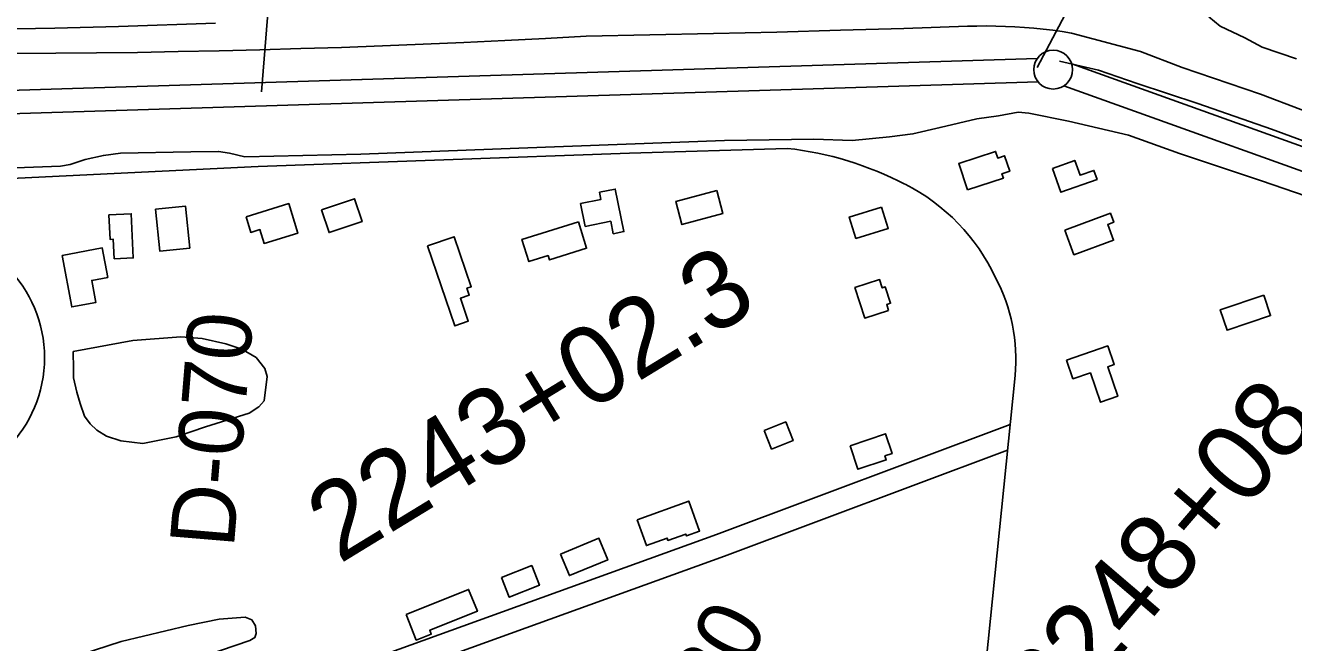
# Model space of a CAD drawing. Extents: x 3540316 to 3578335, y 553172 to 578787.
# Drawn here: x 3546126 to 3547761, y 563019 to 563815 of the extents above; entities that cross this region are included whole.
import ezdxf

# ---------------------------------------------------------------- set-up
doc = ezdxf.new("R2010")
doc.units = 0
for name, color, linetype in [('V-BLDG-OTLN', 7, 'Continuous'), ('V-FLOD-BASE', 7, 'Continuous'), ('V-LEVE-TOET', 7, 'Continuous'), ('V-RIVR-RANG', 7, 'Continuous'), ('V-RIVR-RANG-IDEN', 7, 'Continuous'), ('V-ROAD-CNTR', 7, 'Continuous'), ('V-ROAD-IDEN', 7, 'Continuous'), ('V-SITE-VEGE', 7, 'Continuous'), ('V-SURV-IDEN', 7, 'Continuous'), ('V-SURV-LINE', 7, 'Continuous'), ('V-WETL-SWMP', 7, 'Continuous')]:
    doc.layers.add(name, color=color, linetype=linetype)

msp = doc.modelspace()

# ---------------------------------------------------------------- linework, layer by layer
at = {"layer": 'V-BLDG-OTLN'}
for points in [[(3547340.8, 563603), (3547329.6, 563637.2), (3547377, 563652.8), (3547379.8, 563644.2), (3547388.7, 563647.1), (3547395.3, 563627.2), (3547385.3, 563623.9), (3547387.1, 563618.3)], [(3547450.3, 563630.9), (3547479.2, 563641.1), (3547486, 563622), (3547503.8, 563628.3), (3547507.9, 563616.7), (3547461.1, 563600.2)], [(3546847.9, 563556), (3546841.9, 563585.5), (3546868.1, 563590.9), (3546866.2, 563600), (3546886.5, 563604.1), (3546897.7, 563549.3), (3546884, 563546.5), (3546880.7, 563562.7)], [(3546507.7, 563577.6), (3546550.2, 563591.7), (3546560, 563562.3), (3546517.5, 563548.1)], [(3547017.4, 563602.4), (3547025.3, 563572.5), (3546972.4, 563558.4), (3546964.5, 563588.2)], [(3546233.5, 563571), (3546262.2, 563572.3), (3546264.8, 563515.4), (3546240.3, 563514.3), (3546239.1, 563539.5), (3546235, 563539.3)], [(3546293.6, 563578.3), (3546332.1, 563582.3), (3546337.7, 563528), (3546299.2, 563524)], [(3546410.4, 563568.6), (3546465.4, 563585.4), (3546477, 563547.3), (3546433.6, 563534.1), (3546428.2, 563552), (3546416.5, 563548.4)], [(3547230.1, 563580.8), (3547238.5, 563553.3), (3547196.8, 563540.6), (3547188.4, 563568.1)], [(3547466.3, 563551.3), (3547525.2, 563573.1), (3547529.5, 563561.5), (3547521.8, 563558.6), (3547529.3, 563538.3), (3547478.1, 563519.4)], [(3546839, 563562), (3546849.6, 563527.8), (3546801.5, 563512.8), (3546799.8, 563518.4), (3546775.1, 563510.7), (3546766.2, 563539.3)], [(3546644.2, 563530.8), (3546678.8, 563542.7), (3546700.8, 563478.3), (3546695.2, 563476.3), (3546698.2, 563467.4), (3546686.8, 563463.5), (3546697, 563433.7), (3546679.5, 563427.7)], [(3546173, 563518.6), (3546224.9, 563528.4), (3546232, 563490.3), (3546211.4, 563486.5), (3546216.7, 563458.1), (3546185.5, 563452.3)], [(3547239.1, 563447.8), (3547208.4, 563437.9), (3547195.7, 563477.2), (3547227.5, 563487.4), (3547230.9, 563476.8), (3547234.8, 563478.1), (3547241.6, 563456.9), (3547236.7, 563455.3)], [(3547722.9, 563467.5), (3547731.8, 563441), (3547675.7, 563422.1), (3547666.8, 563448.6)], [(3547468.5, 563383.6), (3547521.8, 563402), (3547530.1, 563377.9), (3547521.6, 563374.9), (3547534.7, 563337), (3547512.3, 563329.3), (3547499.3, 563367.2), (3547476.8, 563359.5)], [(3547078.5, 563292.8), (3547106.3, 563303.9), (3547115.9, 563279.9), (3547088.1, 563268.8)], [(3547189.3, 563273.3), (3547234.9, 563288.6), (3547243.5, 563263.1), (3547234.4, 563260.1), (3547236.1, 563255), (3547199.5, 563242.8)], [(3546914.7, 563177.8), (3546981.2, 563201.9), (3546995.2, 563163.1), (3546978.3, 563157), (3546977.4, 563159.4), (3546954.4, 563151.1), (3546953.3, 563154.1), (3546926.8, 563144.5)], [(3546815.9, 563133.6), (3546865.5, 563153.9), (3546876.9, 563126), (3546827.3, 563105.7)], [(3546739.9, 563103.3), (3546778.9, 563118.6), (3546788.8, 563093.3), (3546749.9, 563077.9)], [(3546616.7, 563055.8), (3546697.4, 563088), (3546708.7, 563059.7), (3546647.3, 563035.2), (3546649.2, 563030.3), (3546629.9, 563022.6)]]:
    msp.add_lwpolyline(points, close=True, dxfattribs=at)
at = {"layer": 'V-FLOD-BASE'}
for points in [[(3547732.8, 563681.3), (3547637.7, 563714.7), (3547559.5, 563740.2), (3547509.8, 563757.5), (3547459.6, 563769.3)], [(3547732.8, 563681.3), (3547859, 563635.1), (3547920.3, 563611.6), (3547936, 563602.3), (3547953.7, 563588.4), (3548014.1, 563528.4), (3548095, 563444.7), (3548172.1, 563357.5), (3548235.3, 563283.4), (3548250.7, 563259.2), (3548264.3, 563231.1), (3548275.4, 563204.2), (3548293.5, 563137.7), (3548316.5, 563043.4), (3548335.6, 562949), (3548357.9, 562845.3), (3548380.5, 562744.8), (3548397.3, 562646.1), (3548408.5, 562557.6), (3548412.6, 562529.5), (3548447.8, 562533.6)]]:
    msp.add_lwpolyline(points, dxfattribs=at)
at = {"layer": 'V-LEVE-TOET'}
for points in [[(3547475, 563805.4), (3547462.9, 563807.3), (3547450.7, 563808.9), (3547438.6, 563810.4), (3547426.4, 563811.6), (3547414.2, 563812.6), (3547402, 563813.4), (3547389.7, 563814), (3547377.5, 563814.3), (3547365.3, 563814.5), (3547353, 563814.4), (3547340.8, 563814.1), (3547258.9, 563811.4), (3547177, 563808.9), (3547095, 563806.7), (3547013.1, 563804.7), (3546931.2, 563802.9), (3546849.2, 563801.3), (3546796.6, 563798.4), (3546744, 563795.7), (3546691.4, 563793.2), (3546638.8, 563790.9), (3546586.2, 563788.8), (3546533.5, 563786.9), (3546480.9, 563785.3), (3546428.2, 563783.8), (3546375.6, 563782.5), (3546322.9, 563781.4), (3546270.3, 563780.5), (3546217.6, 563779.8), (3546164.9, 563779.3), (3546112.3, 563779.1)], [(3547718.8, 563726.6), (3547617.8, 563760.9), (3547563.8, 563781.4), (3547475, 563805.4)], [(3548383.5, 562932.5), (3548355.2, 563056.6), (3548326.2, 563178.3), (3548302.9, 563250.2), (3548279.1, 563296.3), (3548243.1, 563346.6), (3548162.5, 563430.3), (3548078.8, 563518.3), (3547988.9, 563610.5), (3547957.7, 563638.2), (3547942.4, 563644.7), (3547867.7, 563674.4), (3547770.7, 563707), (3547718.8, 563726.6)], [(3546054.6, 563629.4), (3546170.9, 563633.8), (3546183.5, 563635.7), (3546202.8, 563642.2), (3546226.4, 563647.5), (3546248.5, 563650.4), (3546339.2, 563652.3), (3546375, 563652.8), (3546389.1, 563650.3), (3546408.7, 563645.8), (3546558.4, 563649.2), (3546762.3, 563657.1), (3547027.2, 563666.9), (3547142.7, 563668.6), (3547192.2, 563667), (3547240.1, 563671.7), (3547270.4, 563675.3), (3547305.5, 563683.6), (3547352.7, 563694.6), (3547380.6, 563698.7), (3547406.2, 563703.2), (3547420, 563702.2)], [(3547420, 563702.2), (3547470.9, 563691.6), (3547548.5, 563673.6), (3547614.3, 563650.2), (3547720, 563614.9)], [(3547720, 563614.9), (3547850.4, 563570), (3547889.7, 563555.4), (3547907.8, 563546.1), (3547925.9, 563530.9), (3547962.2, 563495.9), (3548006.1, 563447.2), (3548068.5, 563374), (3548127.3, 563307.8), (3548186.9, 563249), (3548202, 563227.6), (3548211.9, 563205.3), (3548222, 563165), (3548227.7, 563128.2), (3548247.1, 563044.1), (3548259, 562973.2)]]:
    msp.add_lwpolyline(points, dxfattribs=at)
at = {"layer": 'V-RIVR-RANG'}
for p, q in [((3546430.3, 563729.5), (3546522.3, 564865.8)), ((3547430.8, 563760.8), (3547839.1, 564540.3))]:
    msp.add_line(p, q, dxfattribs=at)
at = {"layer": 'V-ROAD-CNTR'}
for points in [[(3544480.6, 563535.3), (3544841.1, 563556.7), (3545160.5, 563568.9), (3545632.1, 563597.6), (3546054.3, 563615.1), (3546426.1, 563633.5), (3546904.8, 563650.3), (3547108.1, 563656.7)], [(3547402.2, 563364), (3547364.6, 562991.1), (3547345.6, 562795.1), (3547308.4, 562377.4), (3547299.3, 562297.2), (3547224.8, 561877.1), (3547141, 561402.8), (3547096.3, 561158), (3547027.2, 560870.2), (3546905.4, 560359.7), (3546779.8, 559870.9), (3546717.4, 559577.5), (3546578.2, 559061.2), (3546501.4, 558729.3), (3546466.9, 558591.5)], [(3547395.8, 563300.8), (3547017.2, 563158.8), (3546434.1, 562948.3), (3545928.6, 562759.5), (3545546.7, 562611.8), (3545364, 562539.7), (3544930.7, 562377.5), (3544814, 562333.8), (3544485.1, 562212.7)], [(3547392.4, 563267.5), (3547027.6, 563130.7), (3546444.5, 562920.1), (3545939.2, 562731.4), (3545557.6, 562583.9), (3545374.8, 562511.7), (3544941.2, 562349.4), (3544824.5, 562305.7), (3544495.5, 562184.5)]]:
    msp.add_lwpolyline(points, dxfattribs=at)
for centre, radius, start, end in [((3547060.7, 563227.9), 431.4, 62.4608, 83.6941), ((3547144.1, 563381.4), 256.9, 24.9769, 63.0663), ((3547175.5, 563384.1), 227.6, 354.9349, 27.6932)]:
    msp.add_arc(centre, radius, start, end, dxfattribs=at)
at = {"layer": 'V-ROAD-IDEN'}
msp.add_circle((3545985.5, 563386.7), 165, dxfattribs=at)
at = {"layer": 'V-SITE-VEGE'}
for p, q in [((3547666.7, 563814.2), (3547651.9, 563826.5)), ((3547698.6, 563799.3), (3547666.7, 563814.2)), ((3547720.8, 563787), (3547698.6, 563799.3)), ((3547765, 563772.1), (3547720.8, 563787))]:
    msp.add_line(p, q, dxfattribs=at)
msp.add_lwpolyline([(3546187.5, 563394.9), (3546264.2, 563408.9), (3546326.4, 563413.8), (3546353.6, 563411.6), (3546384.2, 563404.8), (3546404.8, 563397.6), (3546423.3, 563386.9), (3546434.5, 563372.8), (3546437.5, 563362.3), (3546433.7, 563331.3), (3546427, 563323.2), (3546414.5, 563315.1), (3546358, 563297.4), (3546320.2, 563284.5), (3546277.4, 563276.3), (3546248.7, 563279.7), (3546230.5, 563285.7), (3546218.1, 563293.2), (3546209.2, 563301.4), (3546201.9, 563311.2), (3546196.6, 563327.6), (3546192.1, 563342.4), (3546188, 563360.7), (3546187.7, 563372.3)], close=True, dxfattribs=at)
msp.add_lwpolyline([(3546010.5, 562940.4), (3546144.9, 562986.8), (3546249.1, 563020.9), (3546335.5, 563041.4), (3546375.8, 563049.6), (3546409, 563052.1), (3546417.8, 563048.9), (3546422.6, 563040.8), (3546423.6, 563031.2), (3546421.7, 563025.8), (3546415.4, 563022), (3546242.4, 562963.4), (3546140, 562933.2), (3546124.4, 562930.8)], dxfattribs=at)
at = {"layer": 'V-SURV-LINE'}
for points in [[(3545688.6, 563718.2), (3547430.8, 563772.6)], [(3547475.2, 563765.6), (3547913.9, 563608.3)], [(3547431.8, 563742.6), (3545689.5, 563688.3)], [(3547903.8, 563580), (3547465, 563737.3)]]:
    msp.add_lwpolyline(points, dxfattribs=at)
msp.add_circle((3547451.3, 563758.2), 25, dxfattribs=at)
at = {"layer": 'V-WETL-SWMP'}
for p, q in [((3546370.9, 563818.1), (3546246, 563813.7)), ((3546163.9, 563811.7), (3546068.9, 563810.2)), ((3546246, 563813.7), (3546163.9, 563811.7))]:
    msp.add_line(p, q, dxfattribs=at)

# ---------------------------------------------------------------- texts
at = {"layer": 'V-RIVR-RANG-IDEN'}
for s, rotation, p in [('D-070', 85.2293, (3546394.5, 563140.4)), ('D-080', 62.2133, (3546943.7, 562774.4))]:
    msp.add_text(s, height=83, rotation=rotation, dxfattribs=at).set_placement(p)
at = {"layer": 'V-SURV-IDEN'}
for s, rotation, p in [('2243+02.3', 31.4068, (3546530.8, 563120.2)), ('2248+08.4', 49.4575, (3547455.1, 562905.1)), ('2252+71.4', 36.0766, (3547501.8, 562679.8))]:
    msp.add_text(s, height=100, rotation=rotation, dxfattribs=at).set_placement(p)

doc.saveas('drawing.dxf')
